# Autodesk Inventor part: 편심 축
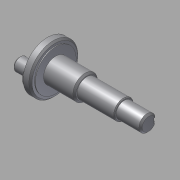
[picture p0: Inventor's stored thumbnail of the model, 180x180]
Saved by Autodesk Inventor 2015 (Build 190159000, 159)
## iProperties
Created: 2015-10
Part Number: 편심 축
Document SubType Name: Modeling
Designer: mdu
Density: 7.86 g/cm^3
Material: 강철, 연강
Mass: 86.2305 g
Surface Area: 42.7652 cm^2
Volume: 10.9708 cm^3
Appearance: 기본값
Author: mdu
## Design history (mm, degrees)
sketch "스케치1"
  geometry: L1 (1.75, -12.001)-(1.75, 11.999) reference; L2 (-16.95, -14)-(-16.95, 14) reference; L3 (-36.25, -18.06)-(-36.25, 18.06) reference; L4 (-41.25, 0)-(20.75, 0); L5 (-41.25, 0)-(-41.25, 15); L6 (-41.25, 15)-(-36.25, 15); L7 (-36.25, 15)-(-36.25, 7.5); L8 (-36.25, 7.5)-(-17.25, 7.5); L9 (-17.25, 6)-(5.75, 6); L10 (20.75, 5)-(20.75, 0); L11 (5.75, 6)-(5.75, 5); L12 (5.75, 5)-(20.75, 5); L13 (-17.25, -13.7)-(-17.25, 13.7) reference; L14 (-17.25, 7.5)-(-17.25, 6); 2 further points
  constraints: 20 end point, 7 perpendicular, 5 point on line, 1 collinear, 1 midpoint, 1 parallel
  dimensions: "d0" = 12 diameter of L9 L4; "d1" = 15 diameter of L8 L4; "d2" = 30 diameter of L6 L4; "d3" = 5 distance of L5.end L6.end; "d4" = 62 distance of L4.start L4.end; "d5" = 10 diameter of L12 L4; "d6" = 15 distance of L11.end L10.start
revolve "회전1" sketch "스케치1" stored, may be unused: angle "d7" = 90 deg
sketch "스케치4"
  geometry: C1 r 15 at (0, 0) reference; C2 r 12.5 at (0, 0); 1 further point
  constraints: 1 centre point, 1 coincident
  dimensions: "d24" = 25 diameter of C2
extrude "돌출4" cut sketch "스케치4" distance "d25" = 0.5; taper "d26" = 0 deg
sketch "스케치2"
  geometry: C1 r 4 at (0, -7.5); C2 r 7.5 at (0, -7.5); C3 r 15 at (0, 0) reference; 1 further point
  constraints: 2 centre point, 1 coincident, 1 tangent, 1 vertical alignment
  dimensions: "d8" = 8 diameter of C1; "d9" = 7.5 distance of point (0, 0) C1.centre
extrude "돌출1" join sketch "스케치2" distance "d10" = 10; taper "d11" = 0 deg
extrude "돌출2" join sketch "스케치2" distance "d12" = 0.5; taper "d13" = 0 deg
node "작업 평면1"
sketch "스케치3"
  geometry: L1 (-7.5, 5)-(-7.5, -5) reference; L2 (-7.5, 1.5)-(3, 1.5); L3 (3, -1.5)-(-7.5, -1.5); A1 r 1.5 centre (3, 0) between (3, -1.5) and (3, 1.5); 2 further points
  constraints: 4 end point, 2 perpendicular, 2 point on circle, 2 point on line, 2 tangent, 1 centre point, 1 horizontal alignment, 1 midpoint
  dimensions: "d14" = 3 distance between parallel lines of L3 L2; "d15" = 12 dimension on A1 L1
extrude "돌출3" cut sketch "스케치3" distance "d16" = 1.8; taper "d17" = 0 deg
chamfer "모따기1" distance "d18" = 1; stored, may be unused: second distance "d19" = 2, angle "d20" = 45 deg
chamfer "모따기2" distance "d21" = 0.5; stored, may be unused: second distance "d22" = 2, angle "d23" = 45 deg
node "솔리드1"
node "참조1"
node "참조2"
node "참조3"
node "참조4"
